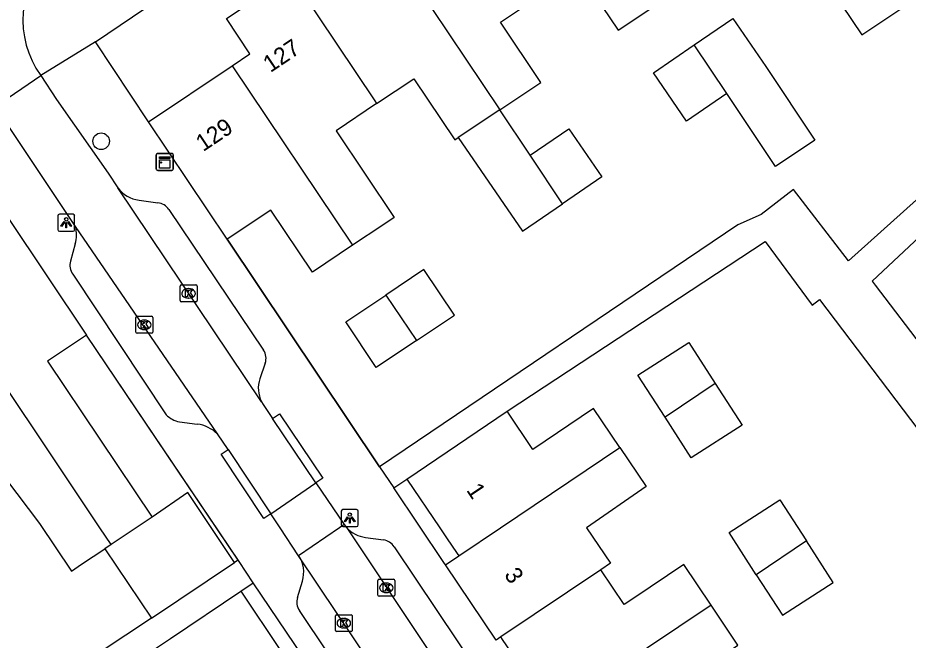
# Model space of a CAD drawing. Extents: x 158352 to 159489, y 383828 to 384597.
# Drawn here: x 158936.2 to 158988.7, y 384243.4 to 384280.1 of the extents above; entities that cross this region are included whole.
import ezdxf

# ---------------------------------------------------------------- set-up
doc = ezdxf.new("R2010")
doc.units = 0
for name, color, linetype in [('IMGEO_Boom', 7, 'Continuous'), ('IMGEO_Kast', 7, 'Continuous'), ('IMGEO_Kolk', 7, 'Continuous'), ('IMGEO_Lichtpunt', 7, 'Continuous'), ('IMGEO_Muur', 7, 'Continuous'), ('IMGEO_Pand', 7, 'Continuous'), ('IMGEO_Pand_nummerreeks', 7, 'Continuous'), ('IMGEO_Rijbaan_lokaal_open', 7, 'Continuous'), ('IMGEO_Voetpad_open', 7, 'Continuous')]:
    doc.layers.add(name, color=color, linetype=linetype)

msp = doc.modelspace()

# ---------------------------------------------------------------- linework, layer by layer
at = {"layer": 'IMGEO_Boom'}
msp.add_circle((158941.13, 384272.801), 0.489, dxfattribs=at)
at = {"layer": 'IMGEO_Kast'}
for p, q in [((158944.384, 384271.159), (158944.384, 384272)), ((158944.384, 384272), (158944.384, 384271.159)), ((158944.459, 384272.084), (158945.3, 384272.084)), ((158945.3, 384272.084), (158944.459, 384272.084)), ((158945.384, 384272.009), (158945.384, 384271.168)), ((158945.384, 384271.168), (158945.384, 384272.009)), ((158945.309, 384271.084), (158944.468, 384271.084)), ((158944.468, 384271.084), (158945.309, 384271.084))]:
    msp.add_line(p, q, dxfattribs=at)
for points in [[(158944.579, 384271.874), (158945.179, 384271.874), (158945.179, 384271.789), (158944.579, 384271.789), (158944.579, 384271.874)], [(158944.579, 384271.699), (158945.179, 384271.699), (158945.179, 384271.21), (158944.579, 384271.21), (158944.579, 384271.699)]]:
    msp.add_lwpolyline(points, dxfattribs=at)
msp.add_circle((158944.663, 384271.548), 0.0377, dxfattribs=at)
for centre, start, end in [((158944.462, 384272.006), 92.4484, 184.2845), ((158944.462, 384272.006), 92.4484, 184.2845), ((158945.306, 384272.006), 2.4484, 94.2845), ((158945.306, 384272.006), 2.4484, 94.2845), ((158944.462, 384271.162), 182.4484, 274.2845), ((158944.462, 384271.162), 182.4484, 274.2845), ((158945.306, 384271.162), 272.4484, 4.2845), ((158945.306, 384271.162), 272.4484, 4.2845)]:
    msp.add_arc(centre, 0.0779, start, end, dxfattribs=at)
at = {"layer": 'IMGEO_Kolk'}
for p, q in [((158945.787, 384263.403), (158945.787, 384264.255)), ((158945.862, 384264.329), (158946.714, 384264.329)), ((158946.275, 384264.109), (158946.3, 384264.109)), ((158946.788, 384264.255), (158946.788, 384263.403)), ((158946.714, 384263.329), (158945.862, 384263.329)), ((158946.298, 384263.549), (158946.273, 384263.549)), ((158943.176, 384261.549), (158943.176, 384262.401)), ((158943.251, 384262.475), (158944.103, 384262.475)), ((158944.177, 384262.401), (158944.177, 384261.549)), ((158943.664, 384262.255), (158943.689, 384262.255)), ((158944.103, 384261.475), (158943.251, 384261.475)), ((158943.687, 384261.695), (158943.662, 384261.695)), ((158957.452, 384246.038), (158957.452, 384246.89)), ((158957.527, 384246.964), (158958.379, 384246.964)), ((158957.94, 384246.744), (158957.965, 384246.744)), ((158958.453, 384246.89), (158958.453, 384246.038)), ((158957.963, 384246.184), (158957.938, 384246.184)), ((158958.379, 384245.964), (158957.527, 384245.964)), ((158954.945, 384243.95), (158954.945, 384244.802)), ((158955.02, 384244.876), (158955.872, 384244.876)), ((158955.433, 384244.656), (158955.458, 384244.656)), ((158955.946, 384244.802), (158955.946, 384243.95)), ((158955.872, 384243.876), (158955.02, 384243.876)), ((158955.456, 384244.096), (158955.431, 384244.096))]:
    msp.add_line(p, q, dxfattribs=at)
for points in [[(158945.787, 384263.403), (158945.787, 384264.255)], [(158945.862, 384264.329), (158946.714, 384264.329)], [(158946.108, 384264.029), (158946.231, 384264.029), (158946.231, 384263.878), (158946.361, 384264.029), (158946.525, 384264.029), (158946.379, 384263.878), (158946.532, 384263.629), (158946.38, 384263.629), (158946.295, 384263.793), (158946.231, 384263.726), (158946.231, 384263.629), (158946.108, 384263.629), (158946.108, 384264.029)], [(158946.788, 384264.255), (158946.788, 384263.403)], [(158946.714, 384263.329), (158945.862, 384263.329)], [(158943.176, 384261.549), (158943.176, 384262.401)], [(158943.251, 384262.475), (158944.103, 384262.475)], [(158944.177, 384262.401), (158944.177, 384261.549)], [(158943.497, 384262.175), (158943.62, 384262.175), (158943.62, 384262.024), (158943.75, 384262.175), (158943.914, 384262.175), (158943.768, 384262.024), (158943.921, 384261.775), (158943.769, 384261.775), (158943.684, 384261.939), (158943.62, 384261.872), (158943.62, 384261.775), (158943.497, 384261.775), (158943.497, 384262.175)], [(158944.103, 384261.475), (158943.251, 384261.475)], [(158957.452, 384246.038), (158957.452, 384246.89)], [(158957.527, 384246.964), (158958.379, 384246.964)], [(158957.773, 384246.664), (158957.896, 384246.664), (158957.896, 384246.513), (158958.026, 384246.664), (158958.19, 384246.664), (158958.044, 384246.513), (158958.197, 384246.264), (158958.045, 384246.264), (158957.96, 384246.428), (158957.896, 384246.361), (158957.896, 384246.264), (158957.773, 384246.264), (158957.773, 384246.664)], [(158958.453, 384246.89), (158958.453, 384246.038)], [(158958.379, 384245.964), (158957.527, 384245.964)], [(158954.945, 384243.95), (158954.945, 384244.802)], [(158955.02, 384244.876), (158955.872, 384244.876)], [(158955.266, 384244.576), (158955.389, 384244.576), (158955.389, 384244.425), (158955.519, 384244.576), (158955.683, 384244.576), (158955.537, 384244.425), (158955.69, 384244.176), (158955.538, 384244.176), (158955.453, 384244.34), (158955.389, 384244.273), (158955.389, 384244.176), (158955.266, 384244.176), (158955.266, 384244.576)], [(158955.946, 384244.802), (158955.946, 384243.95)], [(158955.872, 384243.876), (158955.02, 384243.876)]]:
    msp.add_lwpolyline(points, dxfattribs=at)
for centre, start, end in [((158945.864, 384264.253), 91.552, 178.448), ((158945.864, 384264.253), 91.552, 178.448), ((158946.712, 384264.253), 1.552, 88.448), ((158946.712, 384264.253), 1.552, 88.448), ((158945.864, 384263.405), 181.552, 268.448), ((158945.864, 384263.405), 181.552, 268.448), ((158946.712, 384263.405), 271.552, 358.448), ((158946.712, 384263.405), 271.552, 358.448), ((158943.253, 384262.399), 91.552, 178.448), ((158943.253, 384262.399), 91.552, 178.448), ((158944.101, 384262.399), 1.552, 88.448), ((158944.101, 384262.399), 1.552, 88.448), ((158943.253, 384261.551), 181.552, 268.448), ((158943.253, 384261.551), 181.552, 268.448), ((158944.101, 384261.551), 271.552, 358.448), ((158944.101, 384261.551), 271.552, 358.448), ((158957.529, 384246.888), 91.552, 178.448), ((158957.529, 384246.888), 91.552, 178.448), ((158958.377, 384246.888), 1.552, 88.448), ((158958.377, 384246.888), 1.552, 88.448), ((158957.529, 384246.04), 181.552, 268.448), ((158957.529, 384246.04), 181.552, 268.448), ((158958.377, 384246.04), 271.552, 358.448), ((158958.377, 384246.04), 271.552, 358.448), ((158955.022, 384244.8), 91.552, 178.448), ((158955.022, 384244.8), 91.552, 178.448), ((158955.87, 384244.8), 1.552, 88.448), ((158955.87, 384244.8), 1.552, 88.448), ((158955.022, 384243.952), 181.552, 268.448), ((158955.022, 384243.952), 181.552, 268.448), ((158955.87, 384243.952), 271.552, 358.448), ((158955.87, 384243.952), 271.552, 358.448)]:
    msp.add_arc(centre, 0.0765, start, end, dxfattribs=at)
for centre, major_axis, ratio, start_param, end_param in [((158946.274, 384263.829), (-0.387, 0.002), 0.722429, 4.712389, 7.853982), ((158946.299, 384263.829), (-0.39, 0.002), 0.717154, 1.570796, 4.712389), ((158943.663, 384261.975), (-0.387, 0.002), 0.722429, 4.712389, 7.853982), ((158943.688, 384261.975), (-0.39, 0.002), 0.717154, 1.570796, 4.712389), ((158957.939, 384246.464), (-0.387, 0.002), 0.722429, 4.712389, 7.853982), ((158957.964, 384246.464), (-0.39, 0.002), 0.717154, 1.570796, 4.712389), ((158955.432, 384244.376), (-0.387, 0.002), 0.722429, 4.712389, 7.853982), ((158955.457, 384244.376), (-0.39, 0.002), 0.717154, 1.570796, 4.712389)]:
    msp.add_ellipse(centre, major_axis=major_axis, ratio=ratio, start_param=start_param, end_param=end_param, dxfattribs=at)
at = {"layer": 'IMGEO_Lichtpunt'}
for p, q in [((158938.573, 384268.398), (158938.573, 384267.591)), ((158938.573, 384268.398), (158938.573, 384267.591)), ((158939.475, 384268.493), (158938.667, 384268.493)), ((158939.475, 384268.493), (158938.667, 384268.493)), ((158939.569, 384267.591), (158939.569, 384268.398)), ((158939.569, 384267.591), (158939.569, 384268.398)), ((158938.667, 384267.497), (158939.475, 384267.497)), ((158938.667, 384267.497), (158939.475, 384267.497)), ((158955.296, 384250.981), (158955.296, 384250.174)), ((158955.296, 384250.981), (158955.296, 384250.174)), ((158956.198, 384251.076), (158955.39, 384251.076)), ((158956.198, 384251.076), (158955.39, 384251.076)), ((158956.292, 384250.174), (158956.292, 384250.981)), ((158956.292, 384250.174), (158956.292, 384250.981)), ((158955.39, 384250.08), (158956.198, 384250.08)), ((158955.39, 384250.08), (158956.198, 384250.08))]:
    msp.add_line(p, q, dxfattribs=at)
for points in [[(158938.947, 384268.062), (158938.986, 384268.034), (158938.798, 384267.772), (158938.76, 384267.799), (158938.947, 384268.062)], [(158939.159, 384268.034), (158939.197, 384268.061), (158939.384, 384267.799), (158939.345, 384267.771), (158939.159, 384268.034)], [(158939.049, 384268.014), (158939.096, 384268.014), (158939.096, 384267.692), (158939.049, 384267.692), (158939.049, 384268.014)], [(158955.67, 384250.645), (158955.709, 384250.617), (158955.521, 384250.355), (158955.483, 384250.382), (158955.67, 384250.645)], [(158955.772, 384250.597), (158955.819, 384250.597), (158955.819, 384250.275), (158955.772, 384250.275), (158955.772, 384250.597)], [(158955.882, 384250.617), (158955.92, 384250.644), (158956.107, 384250.382), (158956.068, 384250.354), (158955.882, 384250.617)]]:
    msp.add_lwpolyline(points, dxfattribs=at)
for centre in [(158939.072, 384268.196), (158955.795, 384250.779)]:
    msp.add_circle(centre, 0.0994, dxfattribs=at)
for centre, start, end in [((158938.667, 384268.398), 90, 180), ((158938.667, 384268.398), 90, 180), ((158939.475, 384268.398), 0, 90), ((158939.475, 384268.398), 0, 90), ((158938.667, 384267.591), 180, 270), ((158938.667, 384267.591), 180, 270), ((158939.475, 384267.591), 270, 0), ((158939.475, 384267.591), 270, 360), ((158955.39, 384250.981), 90, 180), ((158955.39, 384250.981), 90, 180), ((158956.198, 384250.981), 0, 90), ((158956.198, 384250.981), 0, 90), ((158955.39, 384250.174), 180, 270), ((158955.39, 384250.174), 180, 270), ((158956.198, 384250.174), 270, 0), ((158956.198, 384250.174), 270, 360)]:
    msp.add_arc(centre, 0.0946, start, end, dxfattribs=at)
at = {"layer": 'IMGEO_Muur'}
for points in [[(158948.56, 384267.017), (158957.557, 384253.607)], [(158949.265, 384248.006), (158940.261, 384261.367)]]:
    msp.add_lwpolyline(points, dxfattribs=at)
at = {"layer": 'IMGEO_Pand'}
for points in [[(158957.624, 384285.128), (158964.64, 384274.654)], [(158986.492, 384283.295), (158984.2, 384281.76), (158986.003, 384279.068), (158988.591, 384280.801)], [(158967.101, 384281.457), (158969.245, 384282.893), (158971.616, 384279.352), (158974.316, 384281.16)], [(158948.863, 384277.257), (158949.909, 384277.957), (158948.515, 384280.038), (158952.317, 384282.584), (158952.783, 384281.887)], [(158952.783, 384281.887), (158957.268, 384275.185), (158957.38, 384275.018)], [(158964.64, 384274.654), (158967.059, 384276.274), (158964.676, 384279.833), (158967.101, 384281.457)], [(158976.11, 384278.481), (158978.385, 384280.041), (158980.332, 384277.201), (158983.234, 384272.871), (158980.911, 384271.315), (158978.027, 384275.62)], [(158978.027, 384275.62), (158975.657, 384273.994), (158973.709, 384276.835), (158976.11, 384278.481)], [(158978.027, 384275.62), (158976.11, 384278.481)], [(158943.919, 384273.946), (158948.863, 384277.257)], [(158948.863, 384277.257), (158955.959, 384266.663)], [(158957.38, 384275.018), (158959.58, 384276.491), (158961.996, 384272.884), (158962.191, 384273.015)], [(158957.38, 384275.018), (158954.989, 384273.417), (158958.412, 384268.305), (158957.747, 384267.86), (158955.959, 384266.663)], [(158964.64, 384274.654), (158962.191, 384273.015)], [(158966.434, 384271.975), (158964.64, 384274.654)], [(158948.56, 384267.017), (158943.919, 384273.946)], [(158966.434, 384271.975), (158968.709, 384273.535), (158970.656, 384270.695), (158968.351, 384269.114)], [(158962.191, 384273.015), (158965.981, 384267.488), (158968.351, 384269.114)], [(158968.351, 384269.114), (158966.434, 384271.975)], [(158955.959, 384266.663), (158953.591, 384265.078), (158951.137, 384268.742), (158948.56, 384267.017)], [(158935.621, 384268.3), (158940.261, 384261.367)], [(158941.716, 384249.009), (158941.052, 384250), (158937.861, 384254.768), (158930.912, 384265.149)], [(158959.726, 384261.039), (158961.971, 384262.543), (158960.168, 384265.235), (158957.923, 384263.731)], [(158959.726, 384261.039), (158957.359, 384259.454), (158955.556, 384262.146), (158957.923, 384263.731)], [(158957.923, 384263.731), (158959.726, 384261.039)], [(158940.261, 384261.367), (158937.976, 384259.839), (158944.137, 384250.629)], [(158974.392, 384256.523), (158972.794, 384259.005), (158975.794, 384260.936), (158977.354, 384258.513)], [(158977.354, 384258.513), (158974.392, 384256.523)], [(158977.354, 384258.513), (158978.933, 384256.06), (158975.934, 384254.129), (158974.392, 384256.523)], [(158929.999, 384256.546), (158932.115, 384257.962), (158935.497, 384252.909), (158937.496, 384250.25), (158939.375, 384247.442), (158939.982, 384247.848), (158941.358, 384248.769)], [(158971.728, 384254.733), (158970.171, 384257.038), (158966.593, 384254.621), (158965.072, 384256.872)], [(158959.158, 384252.878), (158963.302, 384255.677), (158965.072, 384256.872)], [(158962.218, 384248.343), (158964.684, 384250), (158971.728, 384254.733)], [(158971.728, 384254.733), (158973.279, 384252.437), (158969.761, 384250), (158971.168, 384247.907), (158970.609, 384247.531)], [(158959.158, 384252.878), (158961.1, 384250), (158961.499, 384249.409), (158962.123, 384248.483), (158962.218, 384248.343)], [(158949.005, 384247.96), (158946.253, 384252.074), (158944.137, 384250.629)], [(158979.767, 384247.235), (158978.169, 384249.717), (158981.169, 384251.648), (158982.729, 384249.225)], [(158944.137, 384250.629), (158943.197, 384250), (158941.716, 384249.009)], [(158979.767, 384247.235), (158981.309, 384244.841), (158984.308, 384246.772), (158982.729, 384249.225)], [(158982.729, 384249.225), (158979.767, 384247.235)], [(158941.716, 384249.009), (158941.358, 384248.769)], [(158941.358, 384248.769), (158944.095, 384244.676)], [(158961.44, 384247.82), (158962.218, 384248.343)], [(158944.095, 384244.676), (158949.005, 384247.96)], [(158964.714, 384243.57), (158964.426, 384243.377), (158961.44, 384247.82)], [(158977.103, 384245.445), (158975.493, 384247.84), (158972.544, 384245.858), (158971.984, 384245.482), (158970.609, 384247.531)], [(158970.609, 384247.531), (158964.714, 384243.57)], [(158943.393, 384242.254), (158945.215, 384243.478), (158949.365, 384246.266)], [(158949.365, 384246.266), (158951.714, 384242.77), (158952.307, 384241.888), (158952.417, 384241.724)], [(158977.103, 384245.445), (158967.699, 384239.127)], [(158976.552, 384238.626), (158975.155, 384240.705), (158975.34, 384240.83), (158975.759, 384241.111), (158978.691, 384243.081), (158977.103, 384245.445)], [(158967.699, 384239.127), (158965.607, 384242.241), (158964.813, 384243.422), (158964.714, 384243.57)]]:
    msp.add_lwpolyline(points, dxfattribs=at)
at = {"layer": 'IMGEO_Rijbaan_lokaal_open'}
for points in [[(158934.878, 384274.851), (158937.565, 384276.679)], [(158937.565, 384276.679), (158938.496, 384275.255), (158941.545, 384270.918), (158942.113, 384270.058)], [(158939.624, 384267.764), (158937.931, 384270.305), (158934.878, 384274.851)], [(158950.589, 384257.44), (158942.113, 384270.058)], [(158947.99, 384255.54), (158939.624, 384267.764)], [(158950.589, 384257.44), (158950.688, 384257.27), (158951.242, 384256.449)], [(158953.801, 384252.656), (158951.242, 384256.449)], [(158948.621, 384254.614), (158947.99, 384255.54)], [(158948.621, 384254.614), (158951.135, 384250.832)], [(158951.135, 384250.832), (158953.801, 384252.656)], [(158953.801, 384252.656), (158955.463, 384250.193)], [(158952.78, 384248.358), (158951.688, 384250), (158951.135, 384250.832)], [(158955.463, 384250.193), (158955.181, 384250), (158952.78, 384248.358)], [(158955.463, 384250.193), (158955.623, 384249.999)], [(158955.623, 384249.999), (158970.037, 384228.354)], [(158967.539, 384226.335), (158952.78, 384248.358)]]:
    msp.add_lwpolyline(points, dxfattribs=at)
msp.add_arc((158942.143, 384279.951), 5.627, 135.2467, 215.5538, dxfattribs=at)
at = {"layer": 'IMGEO_Voetpad_open'}
for points in [[(158940.799, 384278.671), (158953.222, 384287.087), (158982.278, 384306.539)], [(159003.905, 384282.542), (158985.203, 384265.743), (158981.964, 384269.947), (158980.054, 384268.49), (158978.687, 384267.866), (158957.557, 384253.607)], [(158940.799, 384278.671), (158937.565, 384276.679)], [(158943.919, 384273.946), (158940.799, 384278.671)], [(158996.307, 384273.622), (158986.598, 384264.555), (158986.787, 384264.307), (158989.753, 384260.415), (159001.908, 384244.436), (159013.252, 384254.815)], [(158943.368, 384269.326), (158944.478, 384269.175)], [(158945.119, 384268.776), (158950.706, 384260.485)], [(158957.557, 384253.607), (158948.56, 384267.017)], [(158939.604, 384266.748), (158939.326, 384265.737)], [(158965.072, 384256.872), (158980.303, 384266.882), (158983.065, 384263.142), (158983.504, 384263.466), (158993.796, 384249.884), (158997.206, 384245.844)], [(158939.456, 384264.96), (158944.973, 384256.669)], [(158949.206, 384248.095), (158949.172, 384248.145), (158940.261, 384261.367)], [(158950.808, 384259.719), (158950.492, 384258.789)], [(158951.242, 384256.449), (158951.656, 384256.728), (158954.215, 384252.935), (158953.801, 384252.656)], [(158945.747, 384256.247), (158946.804, 384256.122)], [(158951.135, 384250.832), (158950.719, 384250.556), (158948.205, 384254.338), (158948.621, 384254.614)], [(158957.557, 384253.607), (158958.391, 384252.364)], [(158958.391, 384252.364), (158959.158, 384252.878)], [(158961.44, 384247.82), (158961.346, 384247.96), (158958.391, 384252.364)], [(158956.715, 384249.433), (158957.784, 384249.284)], [(158958.417, 384248.886), (158963.398, 384241.43), (158970.101, 384231.426)], [(158949.206, 384248.095), (158949.005, 384247.96)], [(158950.103, 384246.763), (158949.265, 384248.006), (158949.206, 384248.095)], [(158949.365, 384246.266), (158950.103, 384246.763)], [(158953.16, 384242.224), (158953.05, 384242.388), (158950.103, 384246.763)], [(158952.707, 384245.885), (158953.001, 384246.854)], [(158964.522, 384227.653), (158952.821, 384245.12)], [(158944.095, 384244.676), (158939.5, 384241.627), (158935.13, 384238.626), (158921.579, 384229.323), (158912.32, 384222.965), (158913.229, 384221.576)]]:
    msp.add_lwpolyline(points, dxfattribs=at)
for centre, radius, start, end in [((158943.63, 384271.217), 1.909, 217.3767, 262.1161), ((158944.361, 384268.272), 0.91, 33.5924, 82.6059), ((158937.506, 384267.297), 2.169, 345.3233, 12.4213), ((158940.185, 384265.481), 0.896, 163.4154, 215.581), ((158949.987, 384259.999), 0.868, 341.1366, 34.0331), ((158952.126, 384258.229), 1.728, 161.073, 207.1525), ((158946.051, 384257.726), 1.51, 224.4285, 258.3713), ((158946.455, 384253.911), 2.239, 46.7005, 81.0228), ((158956.966, 384251.253), 1.837, 223.0417, 262.1615), ((158957.658, 384248.381), 0.912, 33.6288, 82.0518), ((158951.297, 384247.372), 1.781, 343.0951, 33.6235), ((158953.572, 384245.623), 0.904, 163.146, 213.8057)]:
    msp.add_arc(centre, radius, start, end, dxfattribs=at)

# ---------------------------------------------------------------- texts
at = {"layer": 'IMGEO_Pand_nummerreeks'}
for s, rotation, p in [('127', 33.8055, (158951.113, 384276.821)), ('129', 33.7889, (158947.145, 384272.158)), ('1', 304.0048, (158962.639, 384252.223)), ('3', 303.9017, (158964.871, 384247.233))]:
    msp.add_text(s, height=1, rotation=rotation, dxfattribs=at).set_placement(p)

doc.saveas('drawing.dxf')
